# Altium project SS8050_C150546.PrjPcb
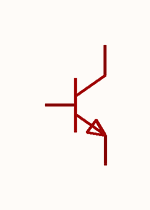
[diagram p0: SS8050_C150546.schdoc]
1 sheet, 1 parts. Net scope: global (net labels, ports and power ports of the same name join across sheets).

## Sheet SS8050_C150546.schdoc
size 127 x 101 mm

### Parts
Q?  ss8050(range:160-300)  [TO-92-3_L5.1-W4.1-P1.27-L]  (value not drawn)

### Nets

Not connected (* = marked no-connect by the designer): Q? 1(E) 2(B) 3(C)

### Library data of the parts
Q? = ss8050(range:160-300): 晶体管类型:NPN;集电极电流(Ic):1.5A;集射极击穿电压(Vceo):25V;耗散功率(Pd):625mW;直流电流增益(hFE):160;; Manufacturer: CJ(江苏长电/长晶); Symbol: SS8050_C150546; AddInBom: yes; ModelId: db569d051dcd4484acf2f9e50678fca3; ModelName: TO-92-3_L4.9-W3.7-P1.27-L; ModelTransform: 180.7872,141.4455,0,0,0,0,0,19.252,-196.85; type: NPN; Current - Collector(Ic): 1.5A; Collector - Emitter Voltage VCEO: 25V; Pd - Power Dissipation: 625mW; DC Current Gain: 160; Transition frequency(fT): 100MHz; Current - Collector Cutoff: 100nA; Vce Saturation(VCE(sat)): 500mV; Emitter-Base Voltage(Vebo): 5V; Number: 1个NPN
